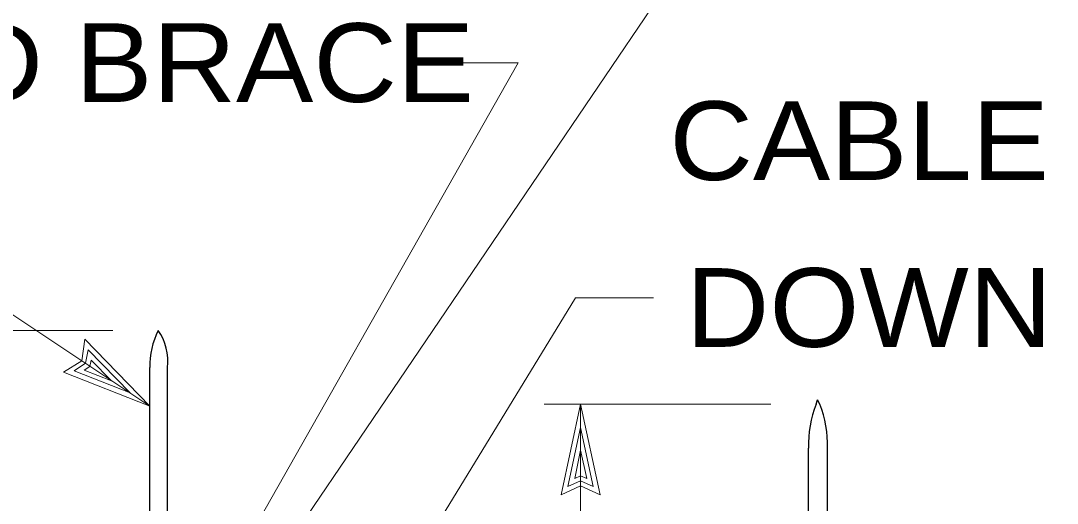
# Model space of a CAD drawing. Extents: x -39.6 to 16.1, y -17.6 to 34.
# Drawn here: x -6.701 to -5.055, y 9.055 to 9.821 of the extents above; entities that cross this region are included whole.
import ezdxf
from ezdxf.enums import TextEntityAlignment as Align

# ---------------------------------------------------------------- set-up
doc = ezdxf.new("R2010")
doc.units = 0
doc.header["$LTSCALE"] = 0.05
doc.layers.add('1', color=7, linetype='Continuous', lineweight=13)

msp = doc.modelspace()

# ---------------------------------------------------------------- linework, layer by layer
at = {"layer": '1'}
for p, q in [((-6.47621, 8.69642), (-5.52221, 10.10342)), ((-6.55521, 9.32942), (-7.33921, 9.32942)), ((-6.49621, 9.20942), (-6.59921, 9.31542)), ((-6.59821, 9.27742), (-6.59421, 9.29842)), ((-6.52721, 9.23042), (-6.59421, 9.29842)), ((-6.61621, 9.26542), (-6.59821, 9.27742)), ((-6.60021, 9.26642), (-6.59121, 9.27242)), ((-6.59121, 9.27242), (-6.58921, 9.28242)), ((-6.55721, 9.24942), (-6.58921, 9.28242)), ((-6.49621, 9.20942), (-6.63321, 9.26342)), ((-6.52721, 9.23042), (-6.61621, 9.26542)), ((-6.55721, 9.24942), (-6.60021, 9.26642)), ((-5.51021, 9.21242), (-5.87021, 9.21242)), ((-5.81221, 9.21242), (-5.84321, 9.06842)), ((-5.81221, 8.43042), (-5.81221, 9.21242)), ((-5.81221, 9.21242), (-5.78121, 9.06842)), ((-5.81221, 9.17542), (-5.83221, 9.08142)), ((-5.81221, 9.17542), (-5.79221, 9.08142)), ((-5.81221, 9.13942), (-5.82121, 9.09442)), ((-5.81221, 9.13942), (-5.80221, 9.09442)), ((-5.81221, 9.09042), (-5.83221, 9.08142)), ((-5.81221, 9.09842), (-5.82121, 9.09442)), ((-5.80221, 9.09442), (-5.81221, 9.09842)), ((-5.79221, 9.08142), (-5.81221, 9.09042))]:
    msp.add_line(p, q, dxfattribs=at)
at = {"layer": '1', "lineweight": 25}
for p, q in [((-6.49621, 8.92842), (-6.49621, 9.27042)), ((-6.46821, 8.92842), (-6.46821, 9.27042)), ((-5.43821, 9.21242), (-5.43621, 9.21942)), ((-5.43221, 9.21242), (-5.43621, 9.21942)), ((-5.45021, 8.81442), (-5.45021, 9.14242)), ((-5.42021, 8.81442), (-5.42021, 9.14242))]:
    msp.add_line(p, q, dxfattribs=at)
at = {"layer": '1'}
for points in [[(-6.42321, 8.85142), (-5.91121, 9.75442), (-6.04621, 9.75442)], [(-6.49621, 9.20942), (-6.87321, 9.46042), (-6.95421, 9.46042)], [(-6.29221, 8.60842), (-5.82021, 9.38142), (-5.69621, 9.38142)], [(-6.63321, 9.26342), (-6.60421, 9.28142), (-6.59921, 9.31542)], [(-5.78121, 9.06842), (-5.81221, 9.08242), (-5.84321, 9.06842)]]:
    msp.add_lwpolyline(points, dxfattribs=at)
at = {"layer": '1', "lineweight": 25}
for centre, radius, start, end in [((-6.36506, 9.27245), 0.13116, 154.25904, 180.88907), ((-6.54997, 9.28104), 0.08245, 352.59855, 35.93047), ((-5.27653, 9.14867), 0.17379, 158.48192, 182.06292), ((-5.59388, 9.14867), 0.17379, 357.93708, 21.51808)]:
    msp.add_arc(centre, radius, start, end, dxfattribs=at)

# ---------------------------------------------------------------- texts
at = {"layer": '1', "width": 1.1}
msp.add_text('TRIPOD BRACE', height=0.125, dxfattribs=at).set_placement((-5.98121, 9.69242), align=Align.RIGHT)
for s, p in [('CABLE CONNECTOR', (-5.67121, 9.56842)), ('DOWN CONDUCTOR', (-5.64521, 9.30342))]:
    msp.add_text(s, height=0.125, dxfattribs=at).set_placement(p)

doc.saveas('drawing.dxf')
